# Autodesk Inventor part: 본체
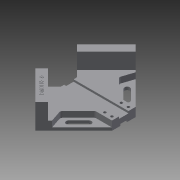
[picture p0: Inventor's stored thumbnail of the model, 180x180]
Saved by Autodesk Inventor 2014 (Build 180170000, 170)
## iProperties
Created: 2019-04
Part Number: 본체
Material: Generic
Document SubType Name: Modeling
Designer: kh
Density: 1 g/cm^3
Appearance: Default
Author: kh
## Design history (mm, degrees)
sketch "Sketch1"
  geometry: L1 (-20, 20)-(20, 20); L2 (20, 20)-(84.853, 84.853); L3 (84.853, 84.853)-(35.355, 134.35); L4 (35.355, 134.35)-(14.005, 113); L5 (14.005, 113)-(-14.005, 113); L6 (0, 20)-(0, 113); L7 (-20, 20)-(-84.853, 84.853); L8 (-84.853, 84.853)-(-35.355, 134.35); L9 (-35.355, 134.35)-(-14.005, 113); L10 (35.355, 134.35)-(-29.885, 199.591); L11 (-35.355, 134.35)-(31.912, 201.618); 1 further point
  constraints: 22 end point, 5 perpendicular, 3 symmetric about line, 2 midpoint, 2 parallel, 1 horizontal, 1 vertical alignment
  dimensions: "d3" = 40 distance of L1.end L1.start; "d39" = 120 distance of point (0, 0) L7.end; "d41" = 20 distance from line of point (0, 0) L1; "d42" = 93 distance between parallel lines of L1 L5; "d43" = 70 distance of L2.end L3.end
extrude "Extrusion1" new body sketch "Sketch1" distance "d11" = 42; taper "d12" = 0 deg
sketch "Sketch2"
  geometry: L1 (20, 20)-(-20, 20) reference; L2 (-20, 20)-(-84.853, 84.853) reference; L3 (-84.853, 84.853)-(-35.355, 134.35) reference; L4 (-35.355, 134.35)-(-14.005, 113) reference; L5 (-14.005, 113)-(14.005, 113) reference; L6 (14.005, 113)-(35.355, 134.35) reference; L7 (35.355, 134.35)-(84.853, 84.853) reference; L8 (84.853, 84.853)-(20, 20) reference; L9 (24.749, 123.744)-(74.246, 74.246); L10 (-74.178, 74.178)-(-24.68, 123.675); L11 (-24.68, 123.675)-(-14.005, 113); L12 (14.005, 113)-(-14.005, 113); L13 (74.246, 74.246)-(20, 20); L14 (20, 20)-(-20, 20); L15 (-20, 20)-(-74.178, 74.178); L16 (14.005, 113)-(24.749, 123.744)
  constraints: 16 end point, 4 perpendicular, 3 collinear, 3 point on line, 1 midpoint
  dimensions: "d46" = 15 distance between parallel lines of L7 L9
extrude "Extrusion2" cut sketch "Sketch2" distance "d15" = 27; taper "d16" = 0 deg
sketch "Sketch3"
  geometry: L1 (-8, 113)-(8, 113); L2 (8, 113)-(8, 20); L3 (8, 20)-(-8, 20); L4 (-8, 20)-(-8, 113); L5 (20, 20)-(-20, 20) reference; 2 further points
  constraints: 8 end point, 2 parallel, 1 horizontal, 1 midpoint, 1 perpendicular, 1 point on line, 1 vertical alignment
  dimensions: "d17" = 16 distance of L2.end L3.end; "d18" = 93 distance of L1.end L2.end
extrude "Extrusion3" cut sketch "Sketch3" distance "d19" = 3.5; taper "d20" = 0 deg
sketch "Sketch4"
  geometry: L1 (-6, 113)-(6, 113); L2 (6, 113)-(6, 20); L3 (6, 20)-(-6, 20); L4 (-6, 20)-(-6, 113); L5 (20, 20)-(-20, 20) reference; 2 further points
  constraints: 8 end point, 2 parallel, 1 horizontal, 1 midpoint, 1 perpendicular, 1 point on line, 1 vertical alignment
  dimensions: "d21" = 12 distance of L1.start L1.end; "d22" = 93 distance of L1.end L2.end
extrude "Extrusion4" cut sketch "Sketch4" distance "d23" = 3; taper "d24" = 0 deg
sketch "Sketch5"
  geometry: L1 (-70.711, 70.711)-(-49.497, 77.782); L2 (-49.497, 77.782)-(-20, 48.284); L3 (-20, 48.284)-(-20, 20); L4 (-20, 20)-(-70.711, 70.711); L5 (-84.853, 84.853)-(-20, 20) reference; L6 (-35.355, 134.35)-(-84.853, 84.853) reference; L7 (8, 20)-(-8, 20) reference; 1 further point
  constraints: 8 end point, 1 collinear, 1 parallel, 1 vertical
  dimensions: "d25" = 20 distance of L1.start L5.start; "d27" = 30 distance from line of L6 L1.end; "d28" = 20 horizontal distance of L3.end point (0, 0); "d29" = 20 distance between parallel lines of L2 L4
extrude "Extrusion5" cut sketch "Sketch5" distance "d30" = 10; taper "d31" = 0 deg
sketch "Sketch6"
  geometry: L1 (-49.497, 63.64)-(-32.527, 46.669); L2 (-52.679, 60.458)-(-35.709, 43.487); L3 (-29.345, 49.851)-(-46.315, 66.822); L4 (-84.853, 84.853)-(-20, 20) reference; L5 (-35.355, 134.35)-(-84.853, 84.853) reference; A1 r 4.5 centre (-49.497, 63.64) between (-46.315, 66.822) and (-52.679, 60.458); A2 r 4.5 centre (-32.527, 46.669) between (-35.709, 43.487) and (-29.345, 49.851); 2 further points
  constraints: 8 end point, 4 point on circle, 4 tangent, 2 centre point, 2 parallel, 1 midpoint
  dimensions: "d32" = 10 distance from line of L1.start L4; "d33" = 40 distance from line of L1.start L5; "d34" = 24 distance of L1.end L1.start; "d35" = 9 distance between parallel lines of L3 L2
extrude "Extrusion6" cut sketch "Sketch6" stored distance "d36" = 10; taper "d37" = 0 deg
mirror "Mirror1"
sketch "Sketch7"
  geometry: L1 (-37.704, 116.532)-(-67.034, 87.201); L2 (-67.034, 87.201)-(-71.898, 92.065); L3 (-71.898, 92.065)-(-42.567, 121.395); L4 (-42.567, 121.395)-(-37.704, 116.532); L5 (-42.567, 121.395)-(-67.034, 87.201); L6 (-35.355, 134.35)-(-84.853, 84.853) reference; L7 (-24.68, 123.675)-(-35.355, 134.35) reference; 2 further points
  constraints: 2 end point, 1 midpoint, 2 other
  dimensions: "d47" = 7.5 distance from line of L6 point (-54.801, 104.298); "d48" = 35 distance from line of L7 point (-54.801, 104.298)
emboss "Emboss1" sketch "Sketch7" dims "d49" = 0.5, "d50" = 0
sketch "Sketch8"
  geometry: L1 (20, 20)-(6, 20) reference; 2 further points
  dimensions: "d51" = 6 distance from line of point (14, 26) L1; "d52" = 14 horizontal distance of point (14, 26) point (0, 0)
hole "Hole1" sketch "Sketch8" at (14, 26) diameter "d53" = 4.5; stored, may be unused: countersink angle "d57" = 90 deg, drill point angle "d59" = 0 deg; dims "d54" = 6, "d55" = 8, "d56" = 10, "d58" = 8
pattern_linear "Rectangular Pattern1" dims "d62" = 28, "d65" = 12
fillet "Fillet1" dims "d66" = 5
fillet "Fillet2" dims "d67" = 5
body "Solid1"
node "Project Cut Edges1"
